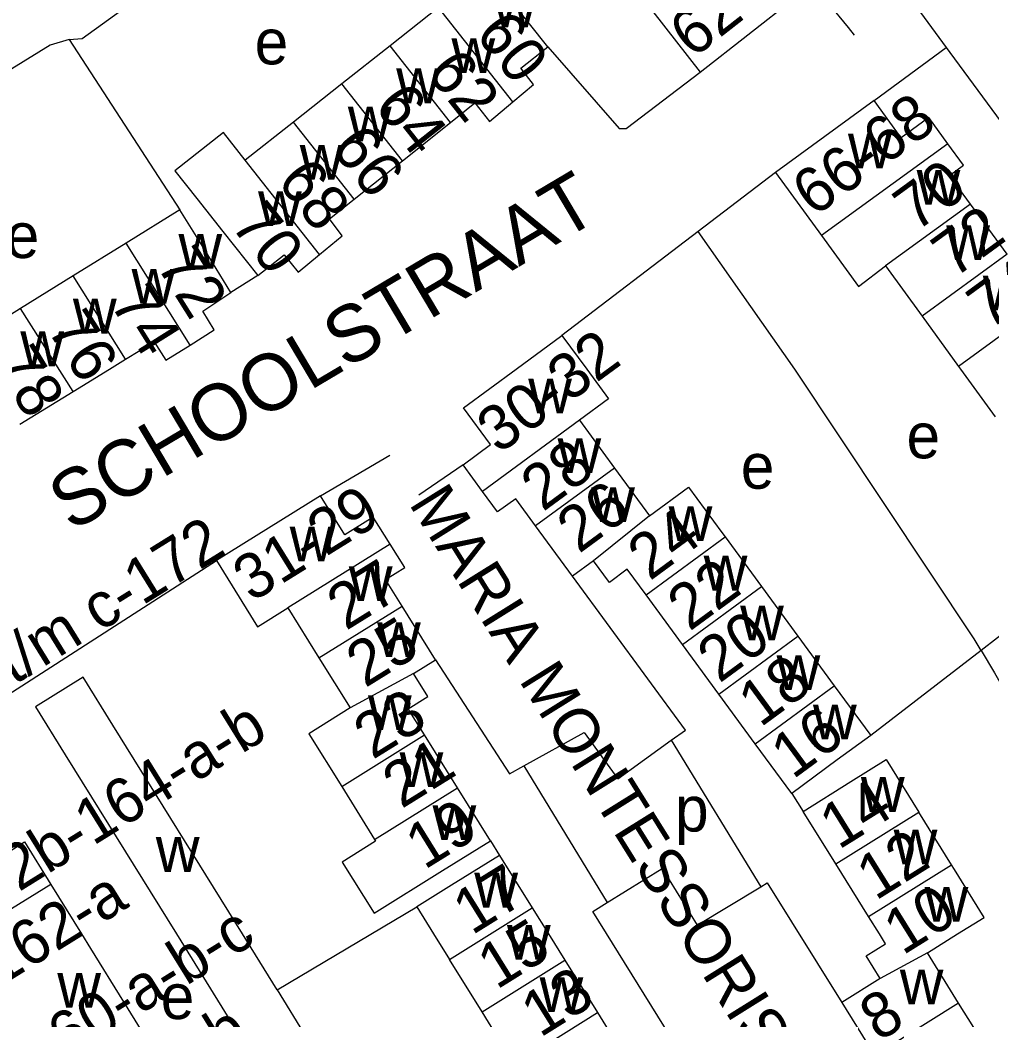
# Model space of a CAD drawing. Extents: x 159902 to 161769, y 383692 to 384875.
# Drawn here: x 160714.3 to 160800.3, y 384242.4 to 384330.9 of the extents above; entities that cross this region are included whole.
import ezdxf

# ---------------------------------------------------------------- set-up
doc = ezdxf.new("R2010")
doc.units = 0
for name, color, linetype in [('BLT_Basislijn', 7, 'Continuous'), ('BLT_Bebouwing', 7, 'Continuous'), ('BLT_Centroide', 7, 'Continuous'), ('BLT_Huisnummer', 7, 'Continuous'), ('BLT_Huisnummer_ tussenligend', 7, 'Continuous'), ('BLT_Huisnummer_reeks', 7, 'Continuous'), ('BLT_Onderverdeling_panden', 7, 'Continuous'), ('BLT_Straatnaam', 7, 'Continuous'), ('BLT_Straatnaam_verkleind', 7, 'Continuous')]:
    doc.layers.add(name, color=color, linetype=linetype)

msp = doc.modelspace()

# ---------------------------------------------------------------- linework, layer by layer
at = {"layer": 'BLT_Basislijn'}
for p, q in [((160793.075, 384332.949), (160796.357, 384328.475)), ((160718.706, 384329.178), (160728.494, 384314.118)), ((160789.979, 384323.771), (160796.357, 384328.475)), ((160781.247, 384317.41), (160774.39, 384312.179)), ((160774.39, 384312.179), (160762.333, 384302.98)), ((160735.391, 384308.28), (160733.02, 384306.773)), ((160740.937, 384288.792), (160747.102, 384292.386)), ((160753.569, 384291.536), (160749.656, 384288.858)), ((160709.793, 384268.957), (160731.733, 384283.055)), ((160809.865, 384283.138), (160799.441, 384275.107)), ((160799.441, 384275.107), (160789.672, 384267.582)), ((160772.014, 384267.152), (160779.94, 384254.178)), ((160758.959, 384264.878), (160766.337, 384252.774)), ((160782.675, 384262.447), (160783.677, 384260.854)), ((160737.098, 384245.063), (160749.467, 384252.395))]:
    msp.add_line(p, q, dxfattribs=at)
for points in [[(160718.706, 384329.178), (160719.845, 384329.26), (160740.708, 384344.361)], [(160788.221, 384329.578), (160787.7, 384330.233), (160785.91, 384332.433), (160784.471, 384334.113)], [(160718.706, 384329.178), (160717.002, 384328.675), (160700, 384318.21)], [(160761.067, 384328.549), (160767.41, 384321.309), (160768.027, 384321.309), (160774.566, 384326.307)], [(160796.357, 384328.475), (160796.681, 384328.033), (160817.323, 384300), (160820.889, 384293.225), (160831.305, 384275.059), (160843.39, 384255.342), (160838.6, 384252.479)], [(160799.441, 384275.107), (160798.836, 384276.117), (160782.953, 384300), (160774.39, 384312.179)], [(160772.014, 384267.152), (160773.266, 384268.054), (160763.263, 384281.684)], [(160799.441, 384275.107), (160800.634, 384273.115), (160818.718, 384241.527)], [(160751.135, 384274.28), (160757.678, 384264.169), (160758.959, 384264.878)], [(160758.959, 384264.878), (160764.295, 384267.83), (160767.279, 384263.74), (160772.014, 384267.152)], [(160766.337, 384252.774), (160771.203, 384255.81), (160774.294, 384250.782), (160779.94, 384254.178)], [(160779.94, 384254.178), (160780.508, 384254.52), (160787.101, 384243.939)], [(160774.825, 384236.266), (160765.077, 384251.988), (160766.337, 384252.774)]]:
    msp.add_lwpolyline(points, dxfattribs=at)
at = {"layer": 'BLT_Bebouwing'}
for p, q in [((160774.566, 384326.307), (160783.117, 384333.004)), ((160751.4, 384332.004), (160747.119, 384328.627)), ((160747.119, 384328.627), (160742.837, 384325.249)), ((160742.837, 384325.249), (160738.556, 384321.872)), ((160789.979, 384323.771), (160781.247, 384317.41)), ((160738.556, 384321.872), (160734.275, 384318.494)), ((160748.204, 384318.451), (160752.467, 384321.851)), ((160743.94, 384315.051), (160748.204, 384318.451)), ((160801.745, 384310.174), (160798.501, 384314.616)), ((160728.494, 384314.118), (160723.729, 384311.169)), ((160723.729, 384311.169), (160719.053, 384308.275)), ((160790.988, 384309.144), (160794.219, 384304.693)), ((160719.053, 384308.275), (160714.376, 384305.38)), ((160714.376, 384305.38), (160709.7, 384302.486)), ((160794.219, 384304.693), (160797.45, 384300.241)), ((160758.272, 384300), (160762.333, 384302.98)), ((160762.333, 384302.98), (160764.52, 384300)), ((160722.253, 384300), (160723.692, 384300.882)), ((160719.051, 384298.037), (160722.253, 384300)), ((160797.45, 384300.241), (160797.625, 384300)), ((160797.625, 384300), (160800.68, 384295.791)), ((160714.314, 384295.132), (160719.051, 384298.037)), ((160763.875, 384295.479), (160766.978, 384291.25)), ((160755.296, 384289.183), (160753.569, 384291.536)), ((160766.978, 384291.25), (160770.082, 384287.021)), ((160740.937, 384288.792), (160731.733, 384283.055)), ((160763.263, 384281.684), (160760, 384286.13)), ((160776.768, 384285.164), (160779.993, 384280.77)), ((160765.121, 384283.047), (160763.263, 384281.684)), ((160772.997, 384275.635), (160769.772, 384280.03)), ((160779.993, 384280.77), (160783.219, 384276.374)), ((160738.054, 384278.87), (160740.813, 384274.443)), ((160751.135, 384274.28), (160748.174, 384279.031)), ((160776.223, 384271.239), (160772.997, 384275.635)), ((160783.219, 384276.374), (160786.445, 384271.979)), ((160740.813, 384274.443), (160743.572, 384270.017)), ((160749.185, 384273.065), (160751.135, 384274.28)), ((160779.448, 384266.844), (160776.223, 384271.239)), ((160786.445, 384271.979), (160789.672, 384267.582)), ((160753.081, 384262.942), (160750.162, 384267.624)), ((160782.675, 384262.447), (160779.448, 384266.844)), ((160742.825, 384263.051), (160745.744, 384258.368)), ((160756, 384258.258), (160753.081, 384262.942)), ((160786.577, 384256.199), (160783.677, 384260.854)), ((160796.829, 384256.125), (160793.93, 384260.78)), ((160756, 384258.258), (160756.792, 384256.961)), ((160756.792, 384256.961), (160759.684, 384252.322)), ((160789.477, 384251.545), (160786.577, 384256.199)), ((160720.592, 384248.714), (160723.517, 384243.997)), ((160797.457, 384243.888), (160794.689, 384248.331)), ((160755.25, 384243.116), (160752.359, 384247.756)), ((160762.576, 384247.682), (160765.467, 384243.043)), ((160790.506, 384246.06), (160787.101, 384243.939)), ((160723.517, 384243.997), (160726.441, 384239.279)), ((160787.101, 384243.939), (160790.02, 384239.254)), ((160800.225, 384239.445), (160797.457, 384243.888)), ((160758.142, 384238.477), (160755.25, 384243.116)), ((160765.467, 384243.043), (160768.359, 384238.404))]:
    msp.add_line(p, q, dxfattribs=at)
for points in [[(160761.067, 384328.549), (160757.964, 384332.47), (160755.67, 384335.373)], [(160772.643, 384333.455), (160770.365, 384331.67), (160774.566, 384326.307)], [(160757.988, 384323.659), (160759.824, 384325.188), (160758.683, 384326.653), (160761.067, 384328.549)], [(160752.467, 384321.851), (160754.622, 384323.569), (160755.914, 384321.931), (160757.988, 384323.659)], [(160796.49, 384319.954), (160794.806, 384322.267), (160792.369, 384320.491), (160789.979, 384323.771)], [(160734.275, 384318.494), (160732.347, 384320.938), (160728.057, 384317.554), (160729.985, 384315.11), (160732.288, 384312.201), (160735.391, 384308.28)], [(160798.501, 384314.616), (160796.645, 384317.157), (160797.875, 384318.053), (160796.49, 384319.954)], [(160781.247, 384317.41), (160785.321, 384311.819)], [(160740.868, 384310.142), (160742.881, 384311.796), (160741.742, 384313.298), (160743.94, 384315.051)], [(160733.02, 384306.773), (160730.427, 384311.049), (160728.494, 384314.118)], [(160785.321, 384311.819), (160788.582, 384307.306), (160790.988, 384309.144)], [(160735.391, 384308.28), (160737.742, 384310.124), (160738.969, 384308.582), (160740.868, 384310.142)], [(160729.397, 384302.136), (160731.544, 384303.483), (160730.53, 384305.14), (160733.02, 384306.773)], [(160723.692, 384300.882), (160726.225, 384302.435), (160727.25, 384300.789), (160729.397, 384302.136)], [(160753.569, 384291.536), (160756.007, 384293.325), (160753.616, 384296.583), (160758.272, 384300)], [(160764.52, 384300), (160766.451, 384297.369), (160763.875, 384295.479)], [(160760, 384286.13), (160758.235, 384288.535), (160756.634, 384287.36), (160755.296, 384289.183)], [(160770.082, 384287.021), (160773.542, 384289.56), (160776.5, 384285.529), (160776.768, 384285.164)], [(160747.117, 384284.519), (160745.626, 384286.911), (160743.093, 384285.332), (160740.937, 384288.792)], [(160748.174, 384279.031), (160746.708, 384281.384), (160748.41, 384282.445), (160747.117, 384284.519)], [(160731.733, 384283.055), (160735.381, 384277.204), (160738.054, 384278.87)], [(160769.772, 384280.03), (160768.113, 384282.29), (160766.53, 384281.128), (160765.121, 384283.047)], [(160750.162, 384267.624), (160748.718, 384269.941), (160750.457, 384271.024), (160749.185, 384273.065)], [(160737.098, 384245.063), (160734.038, 384250), (160722.574, 384268.493), (160719.94, 384272.743), (160715.711, 384270.121), (160718.345, 384265.872), (160728.184, 384250), (160735.463, 384238.256)], [(160743.572, 384270.017), (160739.907, 384267.733), (160742.825, 384263.051)], [(160789.672, 384267.582), (160786.706, 384265.406), (160782.675, 384262.447)], [(160783.677, 384260.854), (160787.922, 384263.498), (160791.031, 384265.434), (160793.93, 384260.78)], [(160713.44, 384257.342), (160714.743, 384258.149), (160717.073, 384254.39)], [(160745.744, 384258.368), (160745.833, 384258.225), (160742.86, 384256.371), (160745.69, 384251.831), (160751.757, 384255.614), (160756, 384258.258)], [(160756.792, 384256.961), (160752.549, 384254.316), (160749.467, 384252.395)], [(160794.689, 384248.331), (160797.368, 384250), (160799.729, 384251.471), (160797.085, 384255.715), (160796.829, 384256.125)], [(160717.073, 384254.39), (160719.795, 384250), (160720.592, 384248.714)], [(160749.467, 384252.395), (160750.96, 384250), (160752.359, 384247.756)], [(160759.684, 384252.322), (160761.131, 384250), (160762.576, 384247.682)], [(160790.506, 384246.06), (160789.256, 384248.066), (160790.976, 384249.137), (160790.439, 384250), (160789.477, 384251.545)], [(160737.098, 384245.063), (160739.692, 384240.878), (160735.463, 384238.256)]]:
    msp.add_lwpolyline(points, dxfattribs=at)
at = {"layer": 'BLT_Onderverdeling_panden'}
for p, q in [((160757.988, 384323.659), (160751.4, 384332.004)), ((160752.467, 384321.851), (160747.119, 384328.627)), ((160748.204, 384318.451), (160742.837, 384325.249)), ((160743.94, 384315.051), (160738.556, 384321.872)), ((160796.49, 384319.954), (160785.321, 384311.819)), ((160740.868, 384310.142), (160734.275, 384318.494)), ((160798.501, 384314.616), (160790.988, 384309.144)), ((160729.397, 384302.136), (160723.729, 384311.169)), ((160801.745, 384310.174), (160794.219, 384304.693)), ((160723.692, 384300.882), (160719.053, 384308.275)), ((160804.989, 384305.732), (160797.45, 384300.241)), ((160719.051, 384298.037), (160714.376, 384305.38)), ((160763.875, 384295.479), (160755.296, 384289.183)), ((160766.978, 384291.25), (160760, 384286.13)), ((160770.082, 384287.021), (160765.121, 384283.047)), ((160747.117, 384284.519), (160738.054, 384278.87)), ((160769.772, 384280.03), (160776.768, 384285.164)), ((160772.997, 384275.635), (160779.993, 384280.77)), ((160740.813, 384274.443), (160748.174, 384279.031)), ((160776.223, 384271.239), (160783.219, 384276.374)), ((160749.185, 384273.065), (160743.572, 384270.017)), ((160779.448, 384266.844), (160786.445, 384271.979)), ((160742.825, 384263.051), (160750.162, 384267.624)), ((160745.744, 384258.368), (160753.081, 384262.942)), ((160786.577, 384256.199), (160793.93, 384260.78)), ((160789.477, 384251.545), (160796.829, 384256.125)), ((160717.073, 384254.39), (160708.983, 384249.377)), ((160752.359, 384247.756), (160759.684, 384252.322)), ((160794.689, 384248.331), (160790.506, 384246.06)), ((160755.25, 384243.116), (160762.576, 384247.682)), ((160797.457, 384243.888), (160790.02, 384239.254)), ((160758.142, 384238.477), (160765.467, 384243.043))]:
    msp.add_line(p, q, dxfattribs=at)

# ---------------------------------------------------------------- texts
at = {"layer": 'BLT_Centroide'}
for s, p in [('w', (160756.234, 384330.266)), ('e', (160735.121, 384326.984)), ('w', (160752.547, 384326.219)), ('w', (160747.656, 384323.547)), ('w', (160743.375, 384320.156)), ('w', (160787.656, 384317.781)), ('w', (160739.109, 384316.781)), ('w', (160793.734, 384314.562)), ('w', (160735.422, 384312.672)), ('e', (160713.076, 384309.84)), ('w', (160796.359, 384309.656)), ('w', (160728.375, 384308.891)), ('w', (160724.219, 384305.797)), ('w', (160799.594, 384305.219)), ('w', (160719.031, 384303.156)), ('w', (160714.375, 384300.266)), ('w', (160759.344, 384296.094)), ('e', (160792.842, 384292.109)), ('w', (160761.938, 384290.812)), ('e', (160778.167, 384289.417)), ('w', (160764.922, 384286.469)), ('w', (160771.781, 384284.781)), ('w', (160738.219, 384283)), ('w', (160774.883, 384280.406)), ('w', (160743.461, 384279.469)), ('w', (160778.109, 384276)), ('w', (160745.961, 384274.531)), ('w', (160781.336, 384271.594)), ('w', (160745.156, 384268.062)), ('w', (160784.562, 384267.219)), ('w', (160747.953, 384263)), ('w', (160788.805, 384260.812)), ('w', (160750.875, 384258.312)), ('p', (160772.344, 384259.07)), ('w', (160791.703, 384256.156)), ('w', (160726.37, 384255.5)), ('w', (160754.57, 384252.344)), ('w', (160794.445, 384251.094)), ('w', (160757.461, 384247.719)), ('w', (160717.648, 384243.469)), ('w', (160792.242, 384243.781)), ('e', (160726.802, 384242.47)), ('w', (160760.352, 384243.094))]:
    msp.add_text(s, height=4, dxfattribs=at).set_placement(p)
at = {"layer": 'BLT_Huisnummer'}
for s, rotation, p in [('60', 308.28554, (160754.559, 384329.647)), ('64', 308.29098, (160745.605, 384323.287)), ('68', 308.3813, (160737.007, 384316.596)), ('72', 36.06757, (160797.028, 384307.979)), ('72', 302.10885, (160726.35, 384309.216)), ('76', 302.48331, (160716.67, 384303.56)), ('28', 36.26879, (160760.641, 384287.327)), ('24', 36.27301, (160770.101, 384281.206)), ('20', 36.27442, (160776.264, 384272.147)), ('23', 31.79738, (160745.566, 384265.392)), ('16', 36.28094, (160782.777, 384263.638)), ('14', 31.92336, (160786.827, 384257.41)), ('19', 31.79738, (160750.148, 384255.641)), ('10', 31.92264, (160792.5, 384248.068)), ('15', 31.89475, (160756.537, 384245.024)), ('8', 31.92706, (160790.371, 384240.413))]:
    msp.add_text(s, height=4, rotation=rotation, dxfattribs=at).set_placement(p)
at = {"layer": 'BLT_Huisnummer_ tussenligend'}
for s, rotation, p in [('62', 308.28554, (160750.224, 384326.256)), ('66', 308.2888, (160741.79, 384319.557)), ('70', 36.06757, (160793.639, 384312.077)), ('70', 308.3813, (160732.901, 384312.738)), ('74', 36.06757, (160800.153, 384303.383)), ('74', 302.10885, (160722.241, 384305.848)), ('78', 301.57157, (160711.963, 384300.476)), ('26', 36.27301, (160763.829, 384283.62)), ('27', 31.78978, (160743.2, 384276.811)), ('22', 36.27442, (160773.62, 384276.742)), ('25', 31.78978, (160744.901, 384271.748)), ('18', 36.28094, (160779.887, 384268.231)), ('21', 31.79738, (160748.12, 384261.042)), ('12', 31.92264, (160790.1, 384252.905)), ('17', 31.89475, (160754.354, 384249.846)), ('13', 31.89541, (160760.39, 384240.78))]:
    msp.add_text(s, height=4, rotation=rotation, dxfattribs=at).set_placement(p)
at = {"layer": 'BLT_Huisnummer_reeks'}
for s, rotation, p in [('62-64', 38.06745, (160773.926, 384327.442)), ('66-68', 36.06481, (160784.649, 384313.419)), ('30-32', 36.27439, (160756.736, 384292.425)), ('31-29', 31.7866, (160734.865, 384279.318)), ('170-a t/m c-172', 31.78978, (160700.915, 384264.01)), ('162b-164-a-b', 31.79555, (160709.182, 384250.558)), ('162-a', 31.79799, (160712.49, 384245.263)), ('160-a-b-c', 31.79407, (160715.917, 384237.237)), ('158a-b', 31.79407, (160720.687, 384231.804))]:
    msp.add_text(s, height=4, rotation=rotation, dxfattribs=at).set_placement(p)
at = {"layer": 'BLT_Straatnaam'}
msp.add_text('SCHOOLSTRAAT', height=5, rotation=30.68233, dxfattribs=at).set_placement((160718.895, 384285.542))
at = {"layer": 'BLT_Straatnaam_verkleind'}
msp.add_text('MARIA MONTESSORISTRAAT', height=4, rotation=301.93653, dxfattribs=at).set_placement((160748.717, 384288.113))

doc.saveas('drawing.dxf')
